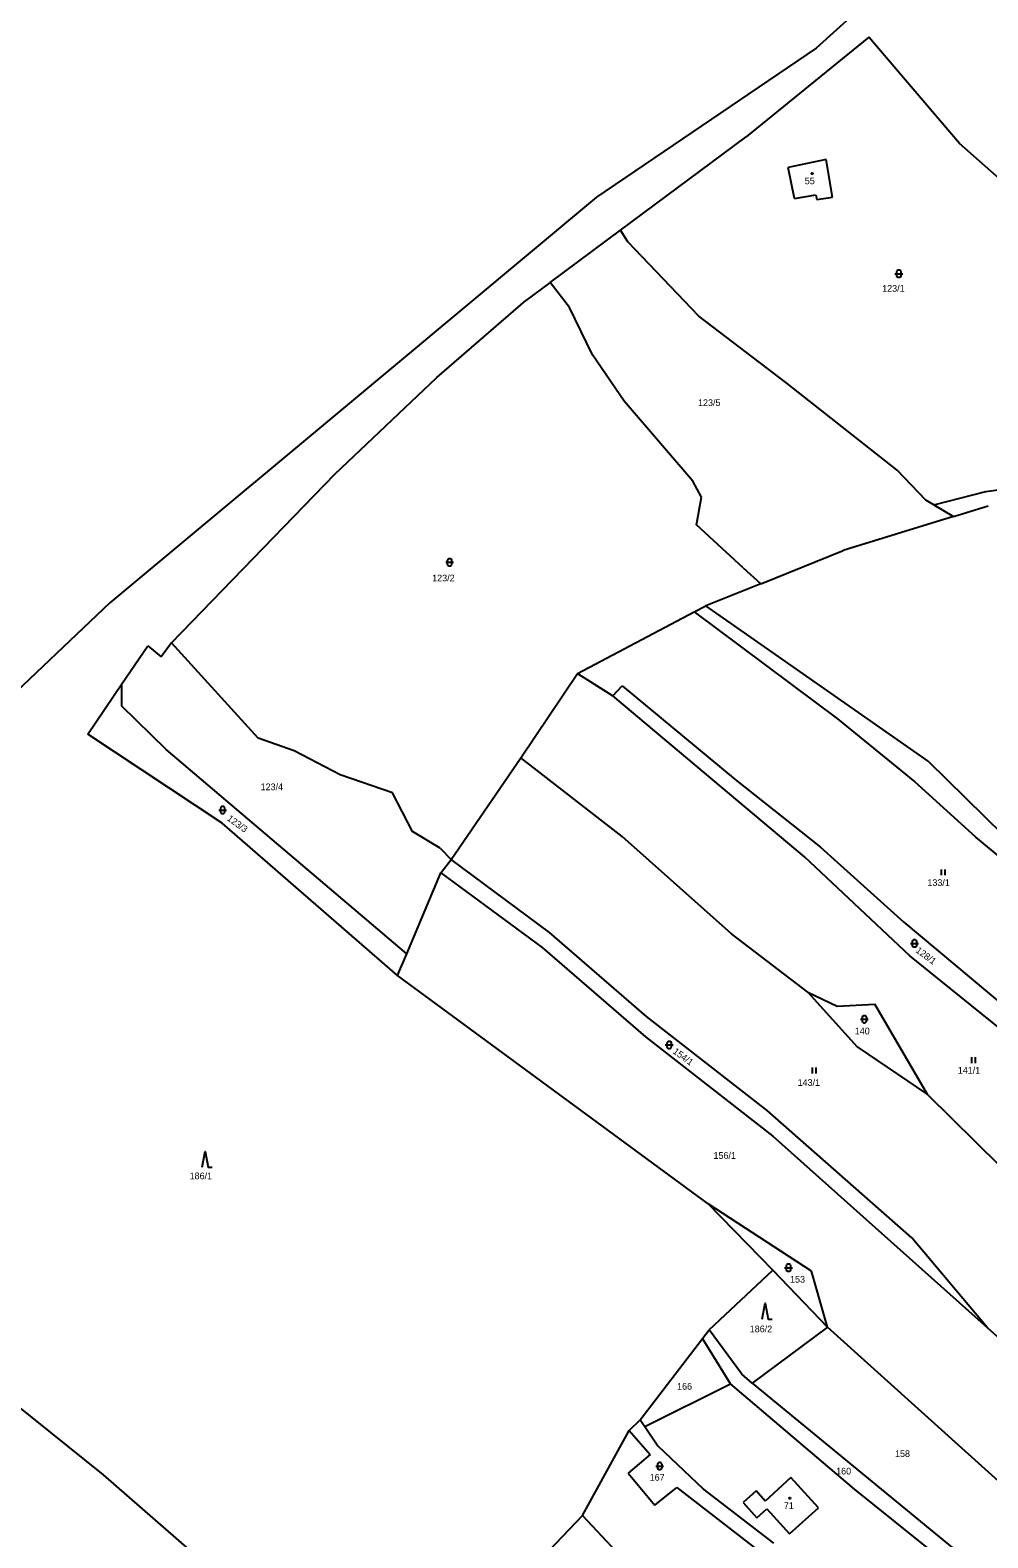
# Model space of a CAD drawing. Extents: x -811039 to -805820, y -1161436 to -1155864.
# Drawn here: x -807214.6 to -806971.7, y -1158370.8 to -1157988.2 of the extents above; entities that cross this region are included whole.
import ezdxf

# ---------------------------------------------------------------- set-up
doc = ezdxf.new("R2010")
doc.units = 0
for name, color, linetype in [('Default', 7, 'Continuous'), ('KN_HRANICE', 7, 'Continuous'), ('KN_KULTURY', 7, 'Continuous'), ('KN_PARCELY', 7, 'Continuous')]:
    doc.layers.add(name, color=color, linetype=linetype)

# ---------------------------------------------------------------- blocks, each defined once
blk = doc.blocks.new('306')
at = {"layer": 'Default'}
for p, q in [((-0.5, 1.5), (-0.5, 0)), ((0.5, 0), (0.5, 1.5))]:
    blk.add_line(p, q, dxfattribs=at)
blk = doc.blocks.new('308')
at = {"layer": 'Default'}
blk.add_lwpolyline([(-0.75, 0), (0, 4), (0.75, 0), (1.75, 0)], dxfattribs=at)
blk = doc.blocks.new('316')
at = {"layer": 'Default'}
for points in [[(-1, 1), (0.27, 1), (1, 1)], [(-0.5, 1.5), (-0.4, 1.79), (-0.15, 1.97), (0.16, 1.97), (0.41, 1.79), (0.51, 1.5), (0.51, 0.5), (0.41, 0.21), (0.16, 0.03), (-0.15, 0.03), (-0.4, 0.21), (-0.5, 0.5), (-0.5, 1.5)]]:
    blk.add_lwpolyline(points, dxfattribs=at)
blk = doc.blocks.new('402')
at = {"layer": 'Default'}
blk.add_lwpolyline([(0.09, 0.15), (0.18, 0), (0.09, -0.15), (-0.09, -0.15), (-0.18, 0), (-0.09, 0.15), (0.09, 0.15)], dxfattribs=at)

msp = doc.modelspace()

# ---------------------------------------------------------------- linework, layer by layer
at = {"layer": 'KN_HRANICE'}
for p, q in [((-806983.04, -1157963.76), (-807015.26, -1157992.79)), ((-806983.04, -1157963.76), (-807015.26, -1157992.79)), ((-807015.26, -1157992.79), (-807070.96, -1158030.65)), ((-807015.26, -1157992.79), (-807070.96, -1158030.65)), ((-807001.87, -1157990.06), (-807032.99, -1158015.3)), ((-806978.9, -1158017.04), (-807001.87, -1157990.06)), ((-807064.85, -1158038.99), (-807032.99, -1158015.3)), ((-806958.71, -1158034.89), (-806978.9, -1158017.04)), ((-807012.73, -1158021.11), (-807022.4, -1158023.12)), ((-807020.75, -1158031), (-807022.4, -1158023.12)), ((-807011.14, -1158030.6), (-807012.73, -1158021.11)), ((-807070.96, -1158030.65), (-807121.92, -1158073.2)), ((-807070.96, -1158030.65), (-807121.92, -1158073.2)), ((-807020.75, -1158031), (-807015.38, -1158030.02)), ((-807015.38, -1158030.02), (-807015.1, -1158031.23)), ((-807015.1, -1158031.23), (-807011.14, -1158030.6)), ((-807082.72, -1158052.28), (-807064.85, -1158038.99)), ((-807063.01, -1158041.98), (-807064.85, -1158038.99)), ((-807044.99, -1158060.79), (-807063.01, -1158041.98)), ((-807082.72, -1158052.28), (-807088.85, -1158056.84)), ((-807077.81, -1158058.66), (-807082.72, -1158052.28)), ((-807111.46, -1158076.42), (-807088.85, -1158056.84)), ((-807071.97, -1158070.67), (-807077.81, -1158058.66)), ((-807022.58, -1158077.9), (-807044.99, -1158060.79)), ((-807121.92, -1158073.2), (-807194.38, -1158133.53)), ((-807121.92, -1158073.2), (-807194.38, -1158133.53)), ((-807063.97, -1158082.38), (-807071.97, -1158070.67)), ((-807137.33, -1158100.94), (-807111.46, -1158076.42)), ((-806994.74, -1158099.86), (-807022.58, -1158077.9)), ((-807046.51, -1158102.69), (-807063.97, -1158082.38)), ((-806987.44, -1158107.47), (-806994.74, -1158099.86)), ((-806972.21, -1158105.33), (-806937.74, -1158100.34)), ((-807178.71, -1158143.71), (-807137.33, -1158100.94)), ((-807044.32, -1158106.75), (-807046.51, -1158102.69)), ((-807045.63, -1158113.72), (-807044.32, -1158106.75)), ((-806985.4, -1158108.7), (-806987.44, -1158107.47)), ((-806985.4, -1158108.7), (-806972.21, -1158105.33)), ((-806980.48, -1158111.68), (-807008.39, -1158120.31)), ((-806985.4, -1158108.7), (-806980.48, -1158111.68)), ((-806980.48, -1158111.68), (-806971.65, -1158108.95)), ((-807033.74, -1158124.65), (-807045.63, -1158113.72)), ((-807029.32, -1158128.7), (-807008.39, -1158120.31)), ((-807033.74, -1158124.65), (-807029.32, -1158128.7)), ((-807029.32, -1158128.7), (-807043.26, -1158134.29)), ((-807194.38, -1158133.53), (-807229.15, -1158166.58)), ((-807194.38, -1158133.53), (-807229.15, -1158166.58)), ((-807046.19, -1158135.84), (-807043.26, -1158134.29)), ((-806986.84, -1158173.73), (-807043.26, -1158134.29)), ((-807075.81, -1158151.48), (-807046.19, -1158135.84)), ((-807046.19, -1158135.84), (-807009.85, -1158162.99)), ((-807191.29, -1158154.12), (-807184.72, -1158144.46)), ((-807184.72, -1158144.46), (-807181.31, -1158147.22)), ((-807178.71, -1158143.71), (-807181.31, -1158147.22)), ((-807156.71, -1158167.86), (-807178.71, -1158143.71)), ((-807090.13, -1158172.9), (-807075.81, -1158151.48)), ((-807075.81, -1158151.48), (-807066.83, -1158157.18)), ((-807199.96, -1158166.86), (-807191.29, -1158154.12)), ((-807191.34, -1158159.77), (-807191.29, -1158154.12)), ((-807066.83, -1158157.18), (-807064.41, -1158154.57)), ((-807018.22, -1158198.03), (-807066.83, -1158157.18)), ((-807064.41, -1158154.57), (-807035.81, -1158178.4)), ((-807180.07, -1158170.75), (-807191.34, -1158159.77)), ((-807009.85, -1158162.99), (-806990.24, -1158178.96)), ((-807165.91, -1158189.47), (-807199.96, -1158166.86)), ((-807147.59, -1158171.14), (-807156.71, -1158167.86)), ((-807119.09, -1158222.61), (-807180.07, -1158170.75)), ((-807135.98, -1158177.21), (-807147.59, -1158171.14)), ((-807107.82, -1158198.66), (-807090.13, -1158172.9)), ((-807064.42, -1158192.88), (-807090.13, -1158172.9)), ((-806986.84, -1158173.73), (-806967.86, -1158192.42)), ((-807122.66, -1158181.8), (-807135.98, -1158177.21)), ((-807035.81, -1158178.4), (-807014.17, -1158195.54)), ((-806974.74, -1158193.03), (-806990.24, -1158178.96)), ((-807117.62, -1158191.59), (-807122.66, -1158181.8)), ((-807121.43, -1158228.14), (-807165.91, -1158189.47)), ((-807110.58, -1158195.76), (-807117.62, -1158191.59)), ((-807110.58, -1158195.76), (-807107.82, -1158198.66)), ((-807036.77, -1158217.51), (-807064.42, -1158192.88)), ((-807014.17, -1158195.54), (-806992.99, -1158214.58)), ((-806954.76, -1158209.69), (-806974.74, -1158193.03)), ((-807110.41, -1158202.06), (-807107.82, -1158198.66)), ((-807082.9, -1158217.2), (-807107.82, -1158198.66)), ((-806991.49, -1158223.13), (-807018.22, -1158198.03)), ((-807119.09, -1158222.61), (-807110.41, -1158202.06)), ((-807110.41, -1158202.06), (-807084.77, -1158220.97)), ((-806992.99, -1158214.58), (-806962.84, -1158239.91)), ((-807058.3, -1158238.51), (-807082.9, -1158217.2)), ((-807017.41, -1158232.31), (-807036.77, -1158217.51)), ((-807121.43, -1158228.14), (-807119.09, -1158222.61)), ((-807084.77, -1158220.97), (-807058.55, -1158243.68)), ((-806967.9, -1158242.14), (-806991.49, -1158223.13)), ((-807042.66, -1158286.07), (-807121.43, -1158228.14)), ((-807017.41, -1158232.31), (-807009.95, -1158235.89)), ((-807017.41, -1158232.31), (-807004.86, -1158246.24)), ((-807009.95, -1158235.89), (-807000.35, -1158235.36)), ((-806987.01, -1158258.28), (-807000.35, -1158235.36)), ((-807027.66, -1158262.37), (-807058.3, -1158238.51)), ((-807058.55, -1158243.68), (-807026.22, -1158268.84)), ((-807004.86, -1158246.24), (-806987.01, -1158258.28)), ((-806987.01, -1158258.28), (-806968.76, -1158276.34)), ((-806990.99, -1158294.65), (-807027.66, -1158262.37)), ((-806971.82, -1158317.52), (-807026.22, -1158268.84)), ((-807016.42, -1158303.1), (-807042.66, -1158286.07)), ((-807042.66, -1158286.07), (-807026.28, -1158302.83)), ((-806971.82, -1158317.52), (-806990.99, -1158294.65)), ((-807042.39, -1158317.98), (-807026.28, -1158302.83)), ((-807026.28, -1158302.83), (-807012.37, -1158317.33)), ((-807012.37, -1158317.33), (-807016.42, -1158303.1)), ((-807044.08, -1158320.18), (-807042.39, -1158317.98)), ((-807034.14, -1158329.27), (-807042.39, -1158317.98)), ((-807012.37, -1158317.33), (-807031.53, -1158331.51)), ((-806956.16, -1158368.04), (-807012.37, -1158317.33)), ((-806937.93, -1158347.83), (-806971.82, -1158317.52)), ((-807059.88, -1158340.81), (-807044.08, -1158320.18)), ((-807037, -1158331.69), (-807044.08, -1158320.18)), ((-807231.93, -1158325.98), (-807196.06, -1158354.81)), ((-807031.53, -1158331.51), (-807034.14, -1158329.27)), ((-807058.67, -1158342.57), (-807037, -1158331.69)), ((-807005.5, -1158358.42), (-807037, -1158331.69)), ((-807031.53, -1158331.51), (-806972.28, -1158380.19)), ((-807062.66, -1158343.51), (-807059.88, -1158340.81)), ((-807059.88, -1158340.81), (-807058.67, -1158342.57)), ((-807074.55, -1158365.1), (-807062.66, -1158343.51)), ((-807062.66, -1158343.51), (-807057.38, -1158349.64)), ((-807058.67, -1158342.57), (-807055.43, -1158347.48)), ((-807055.43, -1158347.48), (-807043.91, -1158358.31)), ((-807057.38, -1158349.64), (-807062.93, -1158354.38)), ((-807196.06, -1158354.81), (-807123.37, -1158417.96)), ((-807062.93, -1158354.38), (-807056.14, -1158362.46)), ((-807021.65, -1158355.47), (-807028.2, -1158361.44)), ((-807014.67, -1158363.18), (-807021.65, -1158355.47)), ((-807056.14, -1158362.46), (-807050.56, -1158358.04)), ((-807050.56, -1158358.04), (-806998.39, -1158398.35)), ((-807026.03, -1158372.13), (-807043.91, -1158358.31)), ((-807030.5, -1158358.9), (-807033.81, -1158361.83)), ((-807028.2, -1158361.44), (-807030.5, -1158358.9)), ((-806975.45, -1158382.58), (-807005.5, -1158358.42)), ((-807033.81, -1158361.83), (-807030.27, -1158365.71)), ((-807030.27, -1158365.71), (-807027.74, -1158363.42)), ((-807027.74, -1158363.42), (-807021.99, -1158369.8)), ((-807021.99, -1158369.8), (-807014.67, -1158363.18)), ((-807074.55, -1158365.1), (-807090.87, -1158382.23)), ((-807074.55, -1158365.1), (-807052.44, -1158388.69))]:
    msp.add_line(p, q, dxfattribs=at)

# ---------------------------------------------------------------- block references
at = {"layer": 'KN_KULTURY'}
for name, p in [('402', (-807016.31, -1158024.6)), ('316', (-806994.29, -1158051.05)), ('316', (-807108.2, -1158124.26)), ('316', (-807165.75, -1158187.12)), ('306', (-806983.05, -1158202.68)), ('316', (-806990.35, -1158220.98)), ('316', (-807003.04, -1158240.19)), ('316', (-807052.51, -1158246.73)), ('306', (-806975.34, -1158250.31)), ('306', (-807015.8, -1158252.98)), ('308', (-807170.19, -1158276.75)), ('316', (-807022.26, -1158303.25)), ('308', (-807028.17, -1158315.28)), ('316', (-807054.93, -1158353.59)), ('402', (-807021.92, -1158360.74))]:
    msp.add_blockref(name, p, dxfattribs=at)

# ---------------------------------------------------------------- texts
at = {"layer": 'KN_PARCELY'}
for s, p in [('55', (-807018.15, -1158027.35)), ('123/1', (-806998.52, -1158054.62)), ('123/5', (-807045.21, -1158083.62)), ('123/2', (-807112.62, -1158128.1)), ('123/4', (-807156.13, -1158181.09)), ('133/1', (-806987.06, -1158205.38)), ('140', (-807005.48, -1158243.05)), ('141/1', (-806979.35, -1158253.01)), ('143/1', (-807019.96, -1158256.11)), ('156/1', (-807041.3, -1158274.63)), ('186/1', (-807174.12, -1158279.8)), ('153', (-807021.88, -1158306.03)), ('186/2', (-807032.1, -1158318.63)), ('166', (-807050.53, -1158333.22)), ('158', (-806995.27, -1158350.28)), ('167', (-807057.48, -1158356.29)), ('160', (-807010.19, -1158354.71)), ('71', (-807023.46, -1158363.46))]:
    msp.add_text(s, height=1.7, dxfattribs=at).set_placement(p)
for s, rotation, p in [('123/3', 324.008, (-807164.79, -1158188.6)), ('128/1', 323.377, (-806990.18, -1158222.06)), ('154/1', 323.836, (-807051.76, -1158247.7))]:
    msp.add_text(s, height=1.7, rotation=rotation, dxfattribs=at).set_placement(p)

doc.saveas('drawing.dxf')
